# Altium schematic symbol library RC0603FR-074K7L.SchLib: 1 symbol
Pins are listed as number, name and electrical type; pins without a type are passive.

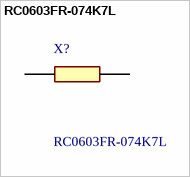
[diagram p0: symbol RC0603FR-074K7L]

## RC0603FR-074K7L
designator X?
YAGEO (PHYCOMP) - RC0603FR-074K7L. - RES, THICK FILM, 4K7, 1%, 0.1W, 0603; Manufacturer_Name: Yageo Group; Geometry.Height: 0.55mm
footprint RESC1608X55N
pins: 1, 2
